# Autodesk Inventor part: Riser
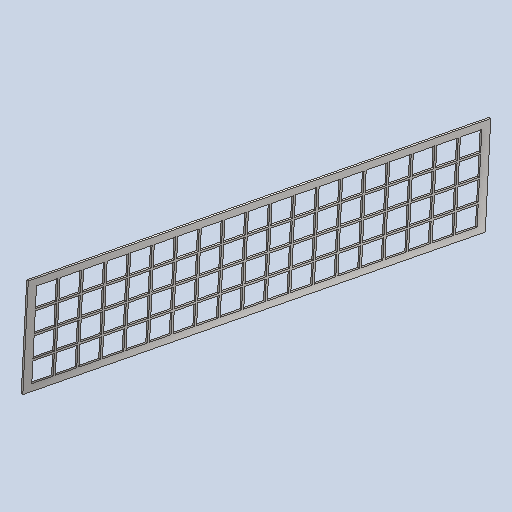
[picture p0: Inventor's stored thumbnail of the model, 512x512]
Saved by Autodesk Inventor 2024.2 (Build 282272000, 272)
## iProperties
RuleStatus: InUse
Created: 2022-06
Part Number: Riser
Material: Aluminum 6061
Document SubType Name: Modeling
Designer: reaumed
Density: 2.7 g/cm^3
Appearance: Aluminum - Flat
Mass: 1140.69 g
Surface Area: 2724.59 cm^2
Volume: 422.479 cm^3
AfterAnyParamChange0: pattern base location
AfterAnyUserParamChange0: pattern base location
Author: reaumed
Material: Steel, Galvanized
Density: 7.85 g/cm^3
Appearance: Galvanized
Mass: 845.798 g
Surface Area: 1112.5 cm^2
Volume: 107.745 cm^3
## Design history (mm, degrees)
workplane "Work Plane1"
sketch "Sketch1"
  geometry: L1 (-342.9, -222.25)-(342.9, -222.25); L2 (342.9, -222.25)-(342.9, -381); L3 (342.9, -381)-(-342.9, -381); L4 (-342.9, -381)-(-342.9, -222.25); 3 further points
  constraints: 8 end point, 2 parallel, 1 coincident, 1 horizontal, 1 midpoint, 1 perpendicular
  dimensions: "ActualRiserWidth" = 685.8 distance of L2.end L3.end (= Width - 2 x StringerThickness); "ActualRiserHeight" = 158.75 distance of L1.end L2.end (= Rise - TreadThickness); "d5" = 222.25 distance from line of L1 point (0, 0) (= Rise + TreadThickness); "d6" = 0 horizontal distance of point (0, 0) point (0, -222.25)
extrude "Extrusion1" new body sketch "Sketch1" distance "d3" = 3.175 (= RiserThickness); taper "d4" = 0 deg
sketch "Sketch2"
  geometry: L1 (233.362, -330.2)-(265.112, -330.2); L2 (265.112, -330.2)-(265.112, -298.45); L3 (265.112, -298.45)-(233.362, -298.45); L4 (233.362, -298.45)-(233.362, -330.2); L5 (233.362, -330.2)-(265.112, -298.45); L6 (381, -342.9)-(381, 342.9) reference; L7 (381, 342.9)-(222.25, 342.9) reference; L8 (381, -342.9)-(222.25, 342.9); 3 further points
  constraints: 12 end point, 2 midpoint, 2 parallel, 1 horizontal, 1 perpendicular
  dimensions: "d7" = 31.75 distance of L2.end L3.end (= HoleSize); "HoleSize" = 31.75 distance of L3.end L1.start; "x_loc" = 314.325 vertical distance of point (249.237, -314.325) point (0, 0); "y_loc" = 52.3875 horizontal distance of point (301.625, 0) point (249.237, -314.325)
extrude "Grating Extrusion" cut sketch "Sketch2" extent not by distance; stored distance "d12" = 0; taper "d13" = 0 deg
body "Solid1"
pattern_linear "Grating Pattern" dims "d16" = 34.925 (= HoleSize + HoleSpacing), "d19" = 34.925 (= HoleSize + HoleSpacing)
other parameters: "Run" = 228.6 [user parameter; used in 1 equation term], "Width" = 762 [user parameter; used in 1 equation term], "Rise" = 190.5 [user parameter; used in 2 equation terms], "TreadThickness" = 31.75 [user parameter; used in 2 equation terms], "RiserThickness" = 3.175 [user parameter; used in 1 equation term], "d0" = 228.6 (= Run), "StringerThickness" = 38.1 [user parameter; used in 1 equation term], "HoleSpacing" = 3.175 [user parameter; used in 2 equation terms]
